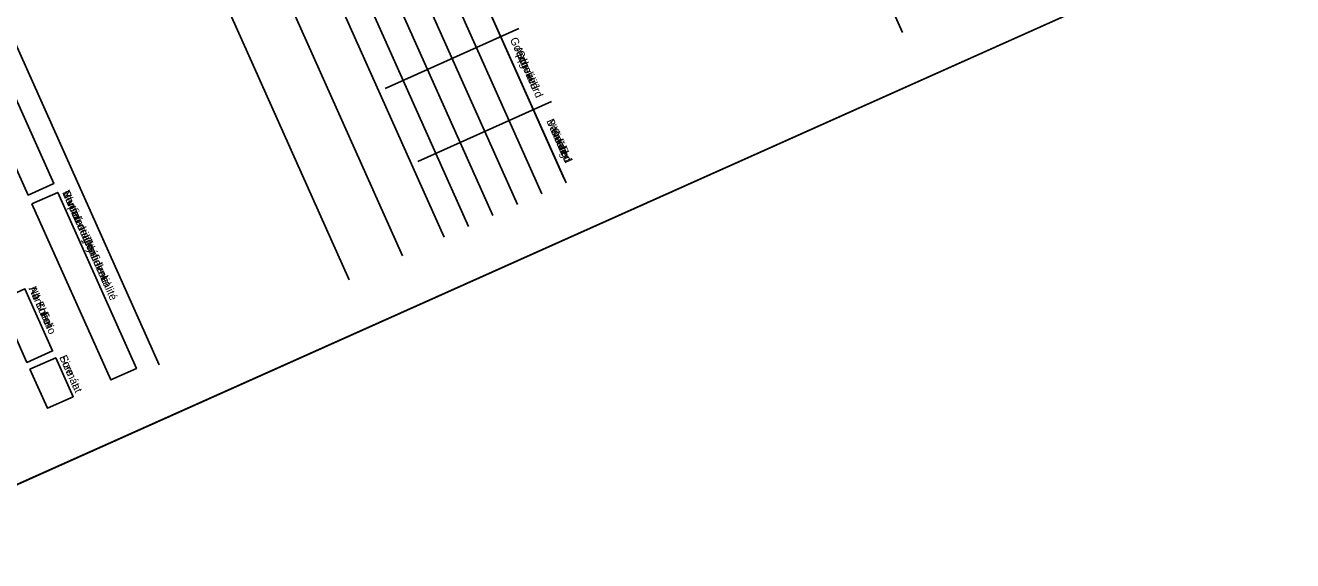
# Model space of a CAD drawing. Extents: x -781656 to -760591, y -1008106 to -975620.
# Drawn here: x -781651.438 to -781646.686, y -1008105.547 to -1008103.54 of the extents above; entities that cross this region are included whole.
import ezdxf

# ---------------------------------------------------------------- set-up
doc = ezdxf.new("R2010")
doc.units = 0
for name, color, linetype in [('Border', 7, 'Continuous'), ('Border_TextCZ', 7, 'Continuous'), ('Border_TextFR', 7, 'Continuous'), ('Border_TextNL', 7, 'Continuous'), ('Border_TextUK', 7, 'Continuous'), ('Výřez', 7, 'Continuous')]:
    doc.layers.add(name, color=color, linetype=linetype)

# ---------------------------------------------------------------- blocks, each defined once
blk = doc.blocks.new('A3coversheet_v03_CZ_1_1')
at = {"layer": 'Border'}
blk.add_line((2.1958, 1.5206), (4.0958, 1.5206), dxfattribs=at)
for points in [[(0, 0), (4.2, 0), (4.2, 2.97), (0, 2.97)], [(3.0734, 0.5905), (3.7134, 0.5905), (3.7134, 0.6434), (3.0734, 0.6434)], [(3.7314, 0.5905), (4.0929, 0.5905), (4.0929, 0.6434), (3.7314, 0.6434)], [(3.8714, 0.4605), (3.9987, 0.4605), (3.9987, 0.5134), (3.8714, 0.5134)], [(4.013, 0.4605), (4.0929, 0.4605), (4.0929, 0.5134), (4.013, 0.5134)]]:
    blk.add_lwpolyline(points, close=True, dxfattribs=at)
for points in [[(2.1958, 2.2115), (4.1042, 2.2115)], [(3.8042, 1.5581), (3.8042, 1.2831)], [(3.9542, 1.5581), (3.9542, 1.2831)], [(2.1958, 1.5206), (4.1042, 1.5206)], [(2.1958, 1.4706), (4.1042, 1.4706)], [(2.1958, 1.4206), (4.1042, 1.4206)], [(2.1958, 1.3706), (4.1042, 1.3706)], [(2.1958, 1.3206), (4.1042, 1.3206)], [(2.1958, 1.2706), (4.1042, 1.2706)], [(2.1958, 1.185), (4.1042, 1.185)], [(2.1958, 1.075), (4.1042, 1.075)], [(2.1958, 0.685), (4.1042, 0.685)]]:
    blk.add_lwpolyline(points, dxfattribs=at)
at = {"layer": 'Border_TextCZ'}
for s, p in [('Schválil', (3.8431, 1.534)), ('Ověřil', (4.0018, 1.534)), ('Stupeň utajení', (3.735, 0.6506)), ('A4', (3.8735, 0.5199)), ('Formát', (4.0146, 0.5197))]:
    blk.add_text(s, height=0.015, dxfattribs=at).set_placement(p)
at = {"layer": 'Border_TextFR'}
for s, p in [('Approuvé', (3.8343, 1.534)), ('Validé', (4, 1.534)), ('Niveau de Confidentialité', (3.735, 0.6506)), ('Nb Folio', (3.8735, 0.5199)), ('Format', (4.0146, 0.5197))]:
    blk.add_text(s, height=0.015, dxfattribs=at).set_placement(p)
at = {"layer": 'Border_TextNL'}
for s, p in [('Goedgekeurd', (3.8157, 1.534)), ('Bevestigd', (3.9831, 1.534)), ('Vertrouwelijkheidlevel', (3.735, 0.6506)), ('Aant. Folio', (3.8735, 0.5199)), ('Formaat', (4.0146, 0.5197))]:
    blk.add_text(s, height=0.015, dxfattribs=at).set_placement(p)
at = {"layer": 'Border_TextUK'}
for s, p in [('Approved', (3.8343, 1.534)), ('Validated', (3.9855, 1.534)), ('Confidentiality Level', (3.735, 0.6506)), ('Nb Sheet', (3.8735, 0.5199)), ('Size', (4.0146, 0.5197))]:
    blk.add_text(s, height=0.015, dxfattribs=at).set_placement(p)

msp = doc.modelspace()

# ---------------------------------------------------------------- linework, layer by layer
at = {"layer": 'Výřez'}
msp.add_lwpolyline([(-781655.5387, -1008097.8791), (-781652.1087, -1008105.5468), (-781646.6865, -1008103.1213), (-781650.1165, -1008095.4535)], close=True, dxfattribs=at)

# ---------------------------------------------------------------- block references
at = {"layer": 'Border', "xscale": 2.0000000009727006, "yscale": 2.0000000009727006, "rotation": -65.8996989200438}
msp.add_blockref('A3coversheet_v03_CZ_1_1', (-781655.5387, -1008097.8791), dxfattribs=at)

doc.saveas('drawing.dxf')
